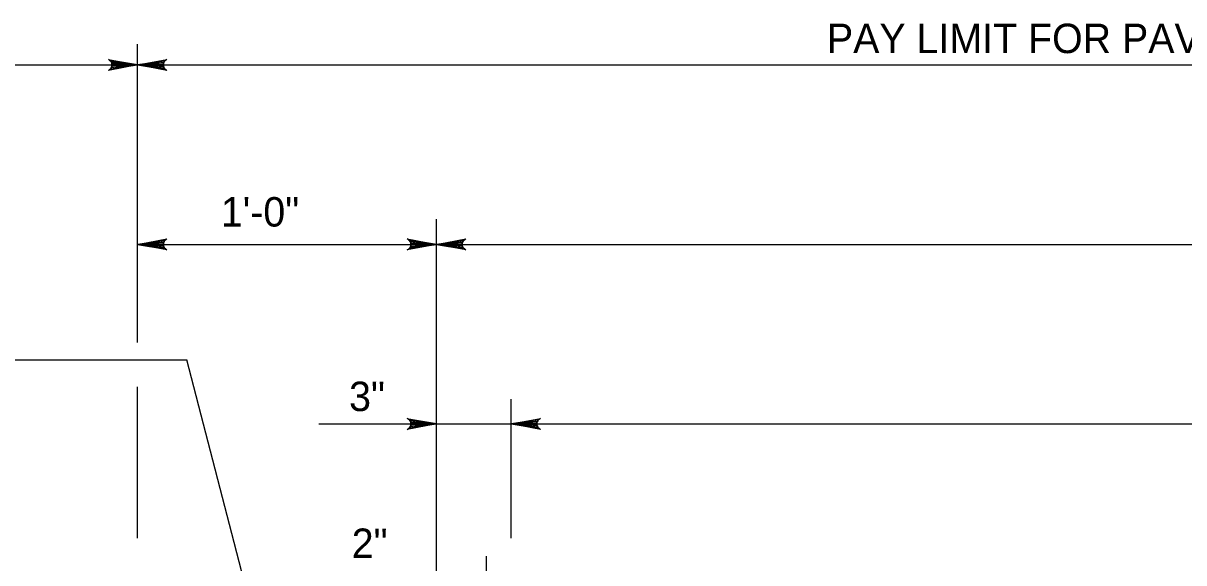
# Model space of a CAD drawing. Extents: x 2084213 to 2099800, y 976677 to 981262.
# Drawn here: x 2094864.1 to 2095252.4, y 979430.6 to 979611 of the extents above; entities that cross this region are included whole.
import ezdxf

# ---------------------------------------------------------------- set-up
doc = ezdxf.new("R2010")
doc.units = 0
doc.layers.add('1', color=7, linetype='Continuous')

msp = doc.modelspace()

# ---------------------------------------------------------------- linework, layer by layer
at = {"layer": '1'}
for p, q in [((2094902.37, 979504.29), (2094902.37, 979604.03)), ((2094519.68, 979597.06), (2094902.37, 979597.06)), ((2094902.37, 979597.06), (2095502.21, 979597.06)), ((2095002.37, 979398), (2095002.37, 979545.46)), ((2094902.37, 979537.06), (2095502.21, 979537.06)), ((2094681.75, 979498.42), (2094918.79, 979498.42)), ((2094948.57, 979383.86), (2094918.79, 979498.42)), ((2094902.37, 979438.9), (2094902.37, 979489.43)), ((2095027.37, 979438.82), (2095027.37, 979485.35)), ((2094962.99, 979477.06), (2095502.21, 979477.06)), ((2095019.04, 979404.17), (2095019.04, 979432.84))]:
    msp.add_line(p, q, dxfattribs=at)
for points in [[(2094902.37, 979597.06), (2094892.59, 979595.23), (2094892.96, 979595.49), (2094893.34, 979595.75), (2094893.53, 979596.08), (2094893.73, 979596.4), (2094893.78, 979596.73), (2094893.84, 979597.06), (2094893.78, 979597.39), (2094893.73, 979597.72), (2094893.53, 979598.04), (2094893.34, 979598.37), (2094892.96, 979598.63), (2094892.59, 979598.9), (2094902.37, 979597.06), (2094892.96, 979598.63), (2094893.34, 979598.37), (2094902.37, 979597.06), (2094893.53, 979598.04), (2094893.73, 979597.72), (2094902.37, 979597.06), (2094893.78, 979597.39), (2094893.84, 979597.06), (2094902.37, 979597.06), (2094893.78, 979596.73), (2094893.73, 979596.4), (2094902.37, 979597.06), (2094893.53, 979596.08), (2094893.34, 979595.75), (2094902.37, 979597.06), (2094892.96, 979595.49)], [(2094902.37, 979597.06), (2094912.16, 979598.9), (2094911.78, 979598.63), (2094911.4, 979598.37), (2094911.21, 979598.04), (2094911.01, 979597.72), (2094910.96, 979597.39), (2094910.9, 979597.06), (2094910.96, 979596.73), (2094911.01, 979596.4), (2094911.21, 979596.08), (2094911.4, 979595.75), (2094911.78, 979595.49), (2094912.16, 979595.23), (2094902.37, 979597.06), (2094911.78, 979595.49), (2094911.4, 979595.75), (2094902.37, 979597.06), (2094911.21, 979596.08), (2094911.01, 979596.4), (2094902.37, 979597.06), (2094910.96, 979596.73), (2094910.9, 979597.06), (2094902.37, 979597.06), (2094910.96, 979597.39), (2094911.01, 979597.72), (2094902.37, 979597.06), (2094911.21, 979598.04), (2094911.4, 979598.37), (2094902.37, 979597.06), (2094911.78, 979598.63)], [(2094902.37, 979537.06), (2094912.16, 979538.9), (2094911.78, 979538.63), (2094911.4, 979538.37), (2094911.21, 979538.04), (2094911.01, 979537.72), (2094910.96, 979537.39), (2094910.9, 979537.06), (2094910.96, 979536.73), (2094911.01, 979536.4), (2094911.21, 979536.08), (2094911.4, 979535.75), (2094911.78, 979535.49), (2094912.16, 979535.23), (2094902.37, 979537.06), (2094911.78, 979535.49), (2094911.4, 979535.75), (2094902.37, 979537.06), (2094911.21, 979536.08), (2094911.01, 979536.4), (2094902.37, 979537.06), (2094910.96, 979536.73), (2094910.9, 979537.06), (2094902.37, 979537.06), (2094910.96, 979537.39), (2094911.01, 979537.72), (2094902.37, 979537.06), (2094911.21, 979538.04), (2094911.4, 979538.37), (2094902.37, 979537.06), (2094911.78, 979538.63)], [(2095002.37, 979537.06), (2094992.59, 979535.23), (2094992.96, 979535.49), (2094993.34, 979535.75), (2094993.53, 979536.08), (2094993.73, 979536.4), (2094993.78, 979536.73), (2094993.84, 979537.06), (2094993.78, 979537.39), (2094993.73, 979537.72), (2094993.53, 979538.04), (2094993.34, 979538.37), (2094992.96, 979538.63), (2094992.59, 979538.9), (2095002.37, 979537.06), (2094992.96, 979538.63), (2094993.34, 979538.37), (2095002.37, 979537.06), (2094993.53, 979538.04), (2094993.73, 979537.72), (2095002.37, 979537.06), (2094993.78, 979537.39), (2094993.84, 979537.06), (2095002.37, 979537.06), (2094993.78, 979536.73), (2094993.73, 979536.4), (2095002.37, 979537.06), (2094993.53, 979536.08), (2094993.34, 979535.75), (2095002.37, 979537.06), (2094992.96, 979535.49)], [(2095002.37, 979537.06), (2095012.16, 979538.9), (2095011.78, 979538.63), (2095011.4, 979538.37), (2095011.21, 979538.04), (2095011.01, 979537.72), (2095010.96, 979537.39), (2095010.9, 979537.06), (2095010.96, 979536.73), (2095011.01, 979536.4), (2095011.21, 979536.08), (2095011.4, 979535.75), (2095011.78, 979535.49), (2095012.16, 979535.23), (2095002.37, 979537.06), (2095011.78, 979535.49), (2095011.4, 979535.75), (2095002.37, 979537.06), (2095011.21, 979536.08), (2095011.01, 979536.4), (2095002.37, 979537.06), (2095010.96, 979536.73), (2095010.9, 979537.06), (2095002.37, 979537.06), (2095010.96, 979537.39), (2095011.01, 979537.72), (2095002.37, 979537.06), (2095011.21, 979538.04), (2095011.4, 979538.37), (2095002.37, 979537.06), (2095011.78, 979538.63)], [(2095002.37, 979477.06), (2094992.59, 979475.23), (2094992.96, 979475.49), (2094993.34, 979475.75), (2094993.53, 979476.08), (2094993.73, 979476.4), (2094993.78, 979476.73), (2094993.84, 979477.06), (2094993.78, 979477.39), (2094993.73, 979477.72), (2094993.53, 979478.04), (2094993.34, 979478.37), (2094992.96, 979478.63), (2094992.59, 979478.9), (2095002.37, 979477.06), (2094992.96, 979478.63), (2094993.34, 979478.37), (2095002.37, 979477.06), (2094993.53, 979478.04), (2094993.73, 979477.72), (2095002.37, 979477.06), (2094993.78, 979477.39), (2094993.84, 979477.06), (2095002.37, 979477.06), (2094993.78, 979476.73), (2094993.73, 979476.4), (2095002.37, 979477.06), (2094993.53, 979476.08), (2094993.34, 979475.75), (2095002.37, 979477.06), (2094992.96, 979475.49)], [(2095027.37, 979477.06), (2095037.16, 979478.9), (2095036.78, 979478.63), (2095036.4, 979478.37), (2095036.21, 979478.04), (2095036.01, 979477.72), (2095035.96, 979477.39), (2095035.9, 979477.06), (2095035.96, 979476.73), (2095036.01, 979476.4), (2095036.21, 979476.08), (2095036.4, 979475.75), (2095036.78, 979475.49), (2095037.16, 979475.23), (2095027.37, 979477.06), (2095036.78, 979475.49), (2095036.4, 979475.75), (2095027.37, 979477.06), (2095036.21, 979476.08), (2095036.01, 979476.4), (2095027.37, 979477.06), (2095035.96, 979476.73), (2095035.9, 979477.06), (2095027.37, 979477.06), (2095035.96, 979477.39), (2095036.01, 979477.72), (2095027.37, 979477.06), (2095036.21, 979478.04), (2095036.4, 979478.37), (2095027.37, 979477.06), (2095036.78, 979478.63)]]:
    msp.add_lwpolyline(points, dxfattribs=at)

# ---------------------------------------------------------------- texts
for s, height, p in [('PAY LIMIT FOR PAVEMENT RELIEF JOINT', 9.8425, (2095132.98, 979601.02)), ('1\'-0"', 9.843, (2094930.2, 979543.03)), ('3"', 9.843, (2094973.11, 979481.34)), ('2"', 9.843, (2094973.99, 979432.23))]:
    msp.add_text(s, height=height, dxfattribs=at).set_placement(p)

doc.saveas('drawing.dxf')
